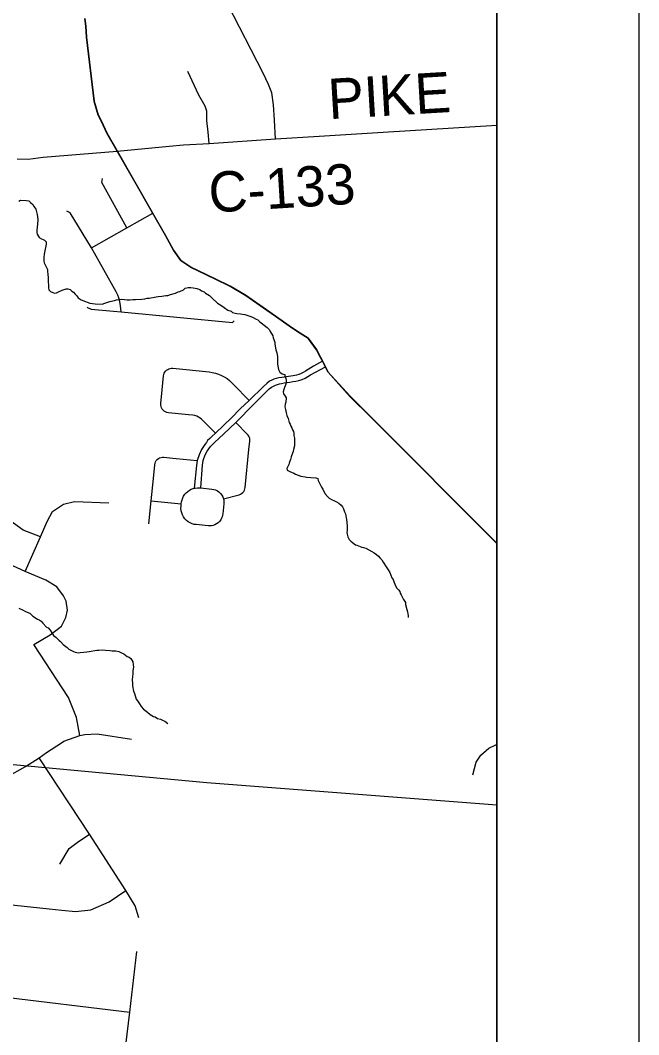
# Model space of a CAD drawing. Extents: x 0 to 34, y 0 to 22.
# Drawn here: x 8.564 to 9, y 19.556 to 20.27 of the extents above; entities that cross this region are included whole.
import ezdxf

# ---------------------------------------------------------------- set-up
doc = ezdxf.new("R2010")
doc.units = 0
for name, color, linetype in [('GM_X_Corporation', 7, 'Continuous'), ('GM_X_County_Road', 7, 'Continuous'), ('GM_X_County_Road_Text', 7, 'Continuous'), ('GM_X_Minor_River', 7, 'Continuous'), ('GM_X_Rail_Line', 7, 'Continuous'), ('GM_X_Township_Road', 7, 'Continuous'), ('SH_Cut_Line', 7, 'Continuous'), ('SH_Data', 7, 'Continuous')]:
    doc.layers.add(name, color=color, linetype=linetype)

msp = doc.modelspace()

# ---------------------------------------------------------------- linework, layer by layer
at = {"layer": 'GM_X_Corporation'}
for points in [[(8.60975, 20.27174), (8.61063, 20.26619), (8.61111, 20.25861), (8.61638, 20.21342), (8.61923, 20.20395), (8.62153, 20.19935), (8.62531, 20.19123), (8.63253, 20.17854), (8.65759, 20.13482), (8.66679, 20.11878), (8.67239, 20.10856), (8.67755, 20.10121), (8.68447, 20.09648), (8.70159, 20.08829), (8.71215, 20.08314), (8.72307, 20.07673), (8.73782, 20.06641), (8.75623, 20.0537), (8.76158, 20.05002), (8.76728, 20.04645), (8.77298, 20.03861), (8.77583, 20.03315), (8.77892, 20.02721), (8.78106, 20.02293), (8.78866, 20.01438), (8.79674, 20.00559), (8.81123, 19.9911), (8.9, 19.9022), (8.9, 20.9)], [(8.9, 18.67664), (8.9, 19.9022), (8.81123, 19.9911), (8.79674, 20.00559), (8.78866, 20.01438), (8.78106, 20.02293), (8.77892, 20.02721), (8.77583, 20.03315), (8.77298, 20.03861), (8.76728, 20.04645), (8.76158, 20.05002), (8.75623, 20.0537), (8.73782, 20.06641), (8.72307, 20.07673), (8.71215, 20.08314), (8.70159, 20.08829), (8.68447, 20.09648), (8.67755, 20.10121), (8.67239, 20.10856), (8.66679, 20.11878), (8.65759, 20.13482), (8.63253, 20.17854), (8.62531, 20.19123), (8.62153, 20.19935), (8.61923, 20.20395), (8.61638, 20.21342), (8.61111, 20.25861), (8.61063, 20.26619), (8.60975, 20.27174)]]:
    msp.add_lwpolyline(points, dxfattribs=at)
at = {"layer": 'GM_X_County_Road'}
for points in [[(8.9, 19.90205), (8.81135, 19.99083), (8.79686, 20.00533), (8.78878, 20.01412), (8.78118, 20.02267), (8.77935, 20.02633), (8.77904, 20.02695), (8.77595, 20.03289), (8.7731, 20.03835), (8.7674, 20.04619), (8.76169, 20.04976), (8.75635, 20.05344), (8.73794, 20.06615), (8.72319, 20.07647), (8.71226, 20.08288), (8.7017, 20.08803), (8.68458, 20.09622), (8.67767, 20.10094), (8.6725, 20.1083), (8.6669, 20.11851), (8.6577, 20.13456), (8.63264, 20.17827), (8.62543, 20.19096), (8.62164, 20.19908), (8.61934, 20.20368), (8.6165, 20.21315), (8.61122, 20.25835), (8.61075, 20.26593), (8.60987, 20.27147)], [(8.63264, 20.17827), (8.66923, 20.18168), (8.67947, 20.18278), (8.69751, 20.18374), (8.74426, 20.18686), (8.77494, 20.18881), (8.82002, 20.1916), (8.9, 20.19657)], [(8.56216, 20.17288), (8.56991, 20.17271), (8.58053, 20.17399), (8.63264, 20.17827)]]:
    msp.add_lwpolyline(points, dxfattribs=at)
at = {"layer": 'GM_X_Minor_River'}
for points in [[(8.56345, 20.14315), (8.56461, 20.14368), (8.56859, 20.14358), (8.57029, 20.14316), (8.57159, 20.14218), (8.57326, 20.14061), (8.57417, 20.13907), (8.57527, 20.13734), (8.57579, 20.13543), (8.57632, 20.13371), (8.5768, 20.13009), (8.57652, 20.1265), (8.57629, 20.12499), (8.57603, 20.12234), (8.576, 20.12101), (8.57635, 20.11986), (8.57762, 20.11756), (8.5793, 20.11656), (8.58043, 20.11615), (8.58156, 20.11556), (8.58267, 20.11439), (8.58263, 20.11287), (8.58218, 20.11042), (8.58197, 20.10929), (8.58152, 20.10683), (8.58131, 20.1057), (8.58086, 20.10325), (8.581, 20.10097), (8.58115, 20.09964), (8.58205, 20.09772), (8.58278, 20.09637), (8.5835, 20.09483), (8.58365, 20.09312), (8.58381, 20.09198), (8.5841, 20.08856), (8.58406, 20.08704), (8.58416, 20.08325), (8.58432, 20.08211), (8.58447, 20.08059), (8.58577, 20.07941), (8.58727, 20.07862), (8.5884, 20.07821), (8.58992, 20.07855), (8.59127, 20.07908), (8.59396, 20.08034), (8.59664, 20.08141), (8.59778, 20.08138), (8.59948, 20.08076), (8.60078, 20.07959), (8.6019, 20.07899), (8.603, 20.07764), (8.60411, 20.07647), (8.60522, 20.07493), (8.60727, 20.07354), (8.61028, 20.07233), (8.61141, 20.07192), (8.61329, 20.0713), (8.61707, 20.07063), (8.6222, 20.0705), (8.62334, 20.07085), (8.62737, 20.07226), (8.63081, 20.07312), (8.63215, 20.07365), (8.63367, 20.0738), (8.63596, 20.07393), (8.63785, 20.07388), (8.63975, 20.07365), (8.64146, 20.0736), (8.64355, 20.07374), (8.64545, 20.07369), (8.65001, 20.07395), (8.65211, 20.07427), (8.65383, 20.07461), (8.65516, 20.07476), (8.66012, 20.07558)], [(8.66012, 20.07558), (8.66145, 20.07592), (8.66412, 20.07623), (8.66698, 20.07654), (8.66831, 20.07669), (8.67022, 20.07721), (8.67367, 20.07826), (8.67559, 20.07916), (8.67674, 20.07951), (8.67942, 20.08058), (8.68059, 20.08168), (8.68269, 20.0822), (8.68441, 20.08234), (8.68611, 20.08211), (8.68762, 20.08188), (8.68875, 20.08147), (8.69083, 20.08085), (8.69213, 20.07987), (8.69382, 20.07925), (8.69494, 20.07827), (8.69755, 20.0765), (8.6996, 20.07474), (8.70331, 20.07123), (8.70555, 20.06984), (8.70797, 20.06807), (8.71059, 20.0663), (8.71285, 20.06548), (8.71397, 20.06469), (8.71585, 20.06408), (8.71698, 20.06386), (8.71945, 20.0636), (8.72096, 20.06337), (8.72248, 20.06333), (8.72474, 20.06252), (8.7268, 20.0617), (8.7285, 20.06109), (8.73056, 20.0599), (8.73169, 20.05949), (8.7328, 20.05832), (8.7341, 20.05734), (8.73615, 20.05577), (8.73819, 20.05401), (8.73986, 20.05245), (8.7404, 20.0513), (8.74223, 20.04822), (8.74257, 20.04688), (8.74363, 20.04382), (8.74379, 20.0423), (8.74444, 20.0383), (8.74515, 20.03619), (8.74546, 20.03353), (8.74561, 20.03201), (8.74556, 20.02992), (8.74552, 20.02841), (8.74586, 20.02688), (8.74602, 20.02555), (8.74618, 20.02441), (8.74727, 20.02249), (8.74896, 20.02149), (8.75065, 20.02107), (8.75081, 20.01974), (8.75153, 20.0182), (8.75169, 20.01687), (8.75165, 20.01554), (8.75143, 20.01422), (8.75042, 20.01178), (8.75001, 20.01047), (8.74958, 20.00877), (8.74974, 20.00725), (8.75103, 20.0057), (8.75157, 20.00455), (8.75149, 20.00152), (8.75088, 20.00001), (8.75064, 19.99812), (8.75117, 19.99621), (8.75168, 19.99392), (8.7522, 19.9922), (8.75309, 19.98991), (8.75379, 19.98723), (8.75451, 19.98589), (8.75505, 19.98455), (8.75559, 19.98339), (8.75613, 19.98205), (8.75685, 19.98071), (8.75701, 19.97956), (8.75716, 19.97804), (8.75749, 19.97614), (8.75765, 19.97481), (8.75755, 19.97083), (8.75691, 19.96819), (8.75668, 19.96668), (8.75609, 19.96556), (8.75526, 19.96292), (8.75464, 19.96104), (8.75423, 19.95991), (8.75382, 19.9586), (8.7536, 19.95747), (8.75221, 19.95485), (8.75237, 19.9537), (8.75424, 19.95271), (8.75706, 19.9515)], [(8.75706, 19.9515), (8.75818, 19.95071), (8.76006, 19.95009), (8.76194, 19.94928), (8.76497, 19.94882), (8.7661, 19.94861), (8.76914, 19.94834), (8.77255, 19.94825), (8.77387, 19.94765), (8.77421, 19.94631), (8.77584, 19.94304), (8.77656, 19.94151), (8.77747, 19.94016), (8.77892, 19.93727), (8.78076, 19.93495), (8.78206, 19.93378), (8.78356, 19.93298), (8.78562, 19.93198), (8.78712, 19.93118), (8.78881, 19.93038), (8.7903, 19.92901), (8.79141, 19.92784), (8.79213, 19.92631), (8.79283, 19.9242), (8.79337, 19.92286), (8.79387, 19.92001), (8.79422, 19.91886), (8.79467, 19.9143), (8.79459, 19.91107), (8.79437, 19.90975), (8.79452, 19.90842), (8.79505, 19.9067), (8.79614, 19.90478), (8.79725, 19.90361), (8.79836, 19.90263), (8.80041, 19.90106), (8.80154, 19.90065), (8.80267, 19.90024), (8.80493, 19.89924), (8.80606, 19.89902), (8.80776, 19.89859), (8.80982, 19.89759), (8.81207, 19.89621), (8.81357, 19.89541), (8.81524, 19.89423), (8.81673, 19.89305), (8.81765, 19.89189), (8.81895, 19.89053), (8.82005, 19.88879), (8.82205, 19.88552), (8.82352, 19.88339), (8.82461, 19.88147), (8.82604, 19.87783), (8.82695, 19.87648), (8.82766, 19.87437), (8.82874, 19.87207), (8.82965, 19.87053), (8.83076, 19.86936), (8.83168, 19.8682), (8.83202, 19.86686), (8.83275, 19.86571), (8.83438, 19.86244), (8.83566, 19.86032), (8.83562, 19.85899), (8.83668, 19.85555), (8.8372, 19.85383), (8.83735, 19.85231), (8.83751, 19.85098), (8.83767, 19.84984)], [(8.56342, 19.85643), (8.56642, 19.85502), (8.56811, 19.85403), (8.57111, 19.85281), (8.57222, 19.85165), (8.57334, 19.85086), (8.57652, 19.84869), (8.57764, 19.84828), (8.57914, 19.8473), (8.58025, 19.84594), (8.58283, 19.84303), (8.58395, 19.84243), (8.58543, 19.84087), (8.58781, 19.83721), (8.58949, 19.83603), (8.59171, 19.83369), (8.59283, 19.83291), (8.59449, 19.83078), (8.59561, 19.83018), (8.59747, 19.82861), (8.59858, 19.82745), (8.60177, 19.82585), (8.60309, 19.82543), (8.60535, 19.82499), (8.6065, 19.82515), (8.61126, 19.8256), (8.61297, 19.82593), (8.61831, 19.82674), (8.61964, 19.8269), (8.6225, 19.82701), (8.62439, 19.82677), (8.62762, 19.82669), (8.62913, 19.82646), (8.63179, 19.82639), (8.63386, 19.82596), (8.63611, 19.82476), (8.63724, 19.82435), (8.63966, 19.82239), (8.64098, 19.82179), (8.64229, 19.821), (8.64355, 19.8185), (8.64403, 19.81488), (8.64377, 19.81224), (8.64373, 19.81072), (8.64347, 19.80788), (8.64325, 19.80637), (8.64335, 19.80295), (8.64351, 19.80162), (8.64417, 19.798), (8.64489, 19.79628), (8.64612, 19.79226), (8.64685, 19.79111), (8.64831, 19.78898), (8.6496, 19.78724), (8.65107, 19.78531), (8.65405, 19.78315), (8.65591, 19.78158), (8.65816, 19.78019), (8.65929, 19.77978), (8.66097, 19.77879), (8.66304, 19.77817), (8.66492, 19.77736), (8.66624, 19.77676), (8.66829, 19.77519)]]:
    msp.add_lwpolyline(points, dxfattribs=at)
at = {"layer": 'GM_X_Rail_Line'}
msp.add_lwpolyline([(8.9, 19.7176), (8.69584, 19.73341), (7.47033, 19.84735), (7.26736, 19.78133), (7.23591, 19.76162), (7.19492, 19.71716), (7.16666, 19.69799), (6.88858, 19.5517)], dxfattribs=at)
at = {"layer": 'GM_X_Township_Road'}
for p, q in [((8.655, 19.91583), (8.6566, 19.93204)), ((8.6566, 19.93204), (8.67781, 19.92994)), ((8.36519, 19.60541), (8.64163, 19.57175))]:
    msp.add_line(p, q, dxfattribs=at)
for points in [[(8.74426, 20.18686), (8.74341, 20.2001), (8.74277, 20.21097), (8.74165, 20.21945), (8.73925, 20.22521), (8.73541, 20.23321), (8.71034, 20.28198)], [(8.69751, 20.18374), (8.6967, 20.19162), (8.6959, 20.19978), (8.6959, 20.20649), (8.69462, 20.20985), (8.69014, 20.21769), (8.6823, 20.23433)], [(8.63941, 20.12419), (8.62186, 20.15629), (8.62234, 20.15893)], [(8.61457, 20.11014), (8.59958, 20.1349), (8.59726, 20.1361)], [(8.61457, 20.11014), (8.63941, 20.12419), (8.6577, 20.13456)], [(8.63549, 20.06511), (8.63497, 20.06935), (8.63462, 20.0723), (8.63375, 20.07507), (8.63306, 20.07689), (8.63185, 20.07915), (8.61457, 20.11014)], [(8.61139, 20.06853), (8.61181, 20.06812), (8.61441, 20.067), (8.63001, 20.06552), (8.63549, 20.06511)], [(8.63549, 20.06511), (8.71394, 20.05761), (8.71508, 20.05871)], [(8.77726, 20.03036), (8.77104, 20.02677), (8.76532, 20.02338), (8.76364, 20.02246), (8.76216, 20.02161), (8.76058, 20.02105), (8.75904, 20.02059), (8.75667, 20.02013), (8.74858, 20.01894), (8.74648, 20.01861), (8.74467, 20.01815), (8.74299, 20.0176), (8.74148, 20.0169), (8.74, 20.01615), (8.73812, 20.01473), (8.73572, 20.01256), (8.72555, 20.00268), (8.7255, 20.00263), (8.71938, 19.99672), (8.7131, 19.99044), (8.70196, 19.97975), (8.70178, 19.97959), (8.69939, 19.97741), (8.69785, 19.97584), (8.69633, 19.97442), (8.69548, 19.97314), (8.69429, 19.97166), (8.69193, 19.96814), (8.69035, 19.9643), (8.68896, 19.96043), (8.68841, 19.95696), (8.6868, 19.94081)], [(8.69152, 19.94105), (8.6927, 19.95719), (8.69295, 19.9587), (8.69316, 19.96042), (8.69362, 19.96172), (8.69434, 19.96361), (8.69513, 19.96528), (8.69606, 19.96688), (8.6971, 19.96851), (8.69836, 19.97015), (8.70126, 19.97296), (8.70772, 19.97929), (8.71627, 19.98713), (8.72881, 20.00018), (8.73523, 20.00639), (8.73737, 20.00857), (8.73972, 20.01083), (8.74123, 20.01193), (8.74278, 20.01285), (8.74417, 20.01352), (8.74568, 20.01402), (8.74702, 20.01444), (8.74849, 20.01469), (8.75037, 20.01499), (8.75226, 20.01528), (8.75432, 20.01566), (8.75629, 20.01599), (8.75855, 20.01629), (8.76069, 20.01679), (8.76291, 20.01746), (8.76505, 20.0183), (8.76874, 20.02065), (8.77935, 20.02633)], [(8.70196, 19.97975), (8.69271, 19.98887), (8.69196, 19.98957), (8.69114, 19.99021), (8.68993, 19.99098), (8.68863, 19.99159), (8.68727, 19.99204), (8.68587, 19.99232), (8.68283, 19.99263), (8.66868, 19.99403), (8.66767, 19.99422), (8.6667, 19.99458), (8.66582, 19.99511), (8.66503, 19.99578), (8.66438, 19.99658), (8.66387, 19.99748), (8.66353, 19.99845), (8.66336, 19.99947), (8.66337, 20.0005), (8.66434, 20.01025), (8.6653, 20.02001), (8.66547, 20.02092), (8.66577, 20.0218), (8.66621, 20.02262), (8.66677, 20.02336), (8.66744, 20.024), (8.6682, 20.02453), (8.66904, 20.02494), (8.66993, 20.02521), (8.67085, 20.02533), (8.67178, 20.02532), (8.69739, 20.02278), (8.69964, 20.02246), (8.70185, 20.02194), (8.70401, 20.02123), (8.7061, 20.02034), (8.7081, 20.01927), (8.71001, 20.01803), (8.71179, 20.01662), (8.71345, 20.01507), (8.71462, 20.01387), (8.7255, 20.00263)], [(8.7075, 19.93331), (8.71845, 19.93623), (8.71941, 19.93658), (8.72029, 19.93709), (8.72108, 19.93775), (8.72174, 19.93853), (8.72226, 19.93941), (8.72262, 19.94036), (8.72281, 19.94137), (8.72544, 19.96803), (8.72604, 19.9741), (8.72606, 19.97496), (8.72596, 19.97581), (8.72574, 19.97664), (8.72539, 19.97743), (8.72494, 19.97816), (8.72439, 19.97882), (8.71627, 19.98713)], [(8.6566, 19.93204), (8.65815, 19.94768), (8.65912, 19.95743), (8.65931, 19.95845), (8.65967, 19.95941), (8.6602, 19.9603), (8.66087, 19.96108), (8.66167, 19.96174), (8.66256, 19.96224), (8.66354, 19.96259), (8.66456, 19.96275), (8.66559, 19.96274), (8.67185, 19.96212), (8.67429, 19.96188), (8.68896, 19.96043)], [(8.57865, 19.90654), (8.56647, 19.91135), (8.55711, 19.91821), (8.55368, 19.92664), (8.55311, 19.93742), (8.55477, 19.94583), (8.5557, 19.95348), (8.55711, 19.9605)], [(8.6063, 19.76663), (8.60397, 19.77939), (8.59843, 19.79347), (8.57389, 19.83083), (8.58535, 19.83769), (8.59331, 19.84378), (8.59643, 19.84971), (8.59768, 19.85501), (8.59674, 19.86125), (8.59474, 19.86498), (8.59013, 19.87144), (8.58228, 19.87605), (8.56774, 19.88229), (8.53953, 19.89515), (8.53525, 19.89831), (8.51411, 19.93013), (8.5075, 19.94054), (8.50516, 19.94289), (8.50332, 19.9436)], [(8.67781, 19.92994), (8.67797, 19.93137), (8.6783, 19.93277), (8.6788, 19.93412), (8.67946, 19.93539), (8.68027, 19.93658), (8.68122, 19.93766), (8.68232, 19.93864), (8.68353, 19.93948), (8.68483, 19.94016), (8.68621, 19.94067), (8.68764, 19.94101), (8.6891, 19.94117), (8.69081, 19.94112), (8.69152, 19.94105), (8.69929, 19.94028), (8.70065, 19.94005), (8.70195, 19.93962), (8.70319, 19.939), (8.70432, 19.93822), (8.70539, 19.93719), (8.7063, 19.93602), (8.70701, 19.93471), (8.7075, 19.93331), (8.70773, 19.93219), (8.70782, 19.93106), (8.70778, 19.92993), (8.70708, 19.92286), (8.70691, 19.92179), (8.70663, 19.92075), (8.70622, 19.91975), (8.70555, 19.91856), (8.70472, 19.91748), (8.70374, 19.91653), (8.70264, 19.91574), (8.70143, 19.91511), (8.70015, 19.91465), (8.69902, 19.91442), (8.69788, 19.91432), (8.69673, 19.91437), (8.68824, 19.91521), (8.68693, 19.91541), (8.68542, 19.91584), (8.68399, 19.91646), (8.68264, 19.91727), (8.68142, 19.91825), (8.68033, 19.91939), (8.67941, 19.92065), (8.67866, 19.92203), (8.6781, 19.9235), (8.67774, 19.92502), (8.67758, 19.92658), (8.67763, 19.92815), (8.67777, 19.92958)], [(8.56774, 19.88229), (8.57865, 19.90654), (8.58337, 19.91734), (8.58716, 19.92458), (8.59471, 19.9296), (8.60267, 19.93148), (8.62686, 19.93069)], [(8.46726, 19.73178), (8.49211, 19.72991), (8.4992, 19.72856), (8.50817, 19.72846), (8.5242, 19.72907), (8.53219, 19.73034), (8.53972, 19.73228), (8.54582, 19.73436), (8.55468, 19.73741), (8.56801, 19.745), (8.57767, 19.7511), (8.58296, 19.75466), (8.59338, 19.76156)], [(8.59338, 19.76156), (8.59499, 19.76263), (8.6063, 19.76663), (8.60981, 19.76744), (8.61862, 19.76783), (8.64278, 19.76403)], [(8.88323, 19.73896), (8.88557, 19.74803), (8.88868, 19.75282), (8.89451, 19.75788), (8.8993, 19.76021), (8.9, 19.76032)], [(8.64798, 19.63827), (8.64538, 19.6468), (8.63882, 19.6575), (8.6131, 19.69714), (8.57767, 19.7511)], [(8.59232, 19.6761), (8.59876, 19.68712), (8.60444, 19.69146), (8.6131, 19.69714)], [(8.45919, 19.67404), (8.46398, 19.67311), (8.47051, 19.67057), (8.47714, 19.66658), (8.48172, 19.66386), (8.48944, 19.65885), (8.502, 19.65427), (8.51355, 19.65308), (8.54088, 19.6496), (8.56048, 19.64714), (8.58467, 19.64459), (8.59375, 19.64366), (8.60326, 19.64273), (8.61411, 19.6439), (8.62694, 19.64952), (8.63882, 19.6575)], [(8.63265, 19.49841), (8.63317, 19.5014), (8.63515, 19.51944), (8.64163, 19.57175), (8.64657, 19.61448)]]:
    msp.add_lwpolyline(points, dxfattribs=at)
at = {"layer": 'SH_Cut_Line'}
msp.add_lwpolyline([(8.9, 14.1), (8.9, 20.9), (5.67696, 20.9)], dxfattribs=at)
at = {"layer": 'SH_Data'}
for p, q in [((9, 21), (9, 14)), ((8.9, 20.9), (8.9, 14.1))]:
    msp.add_line(p, q, dxfattribs=at)

# ---------------------------------------------------------------- texts
at = {"layer": 'GM_X_County_Road_Text'}
for s, rotation, p in [('PIKE', 3.40358, (8.78194, 20.20073)), ('C-133', 3.57607, (8.69788, 20.13488))]:
    msp.add_text(s, height=0.028409, rotation=rotation, dxfattribs=at).set_placement(p)

doc.saveas('drawing.dxf')
